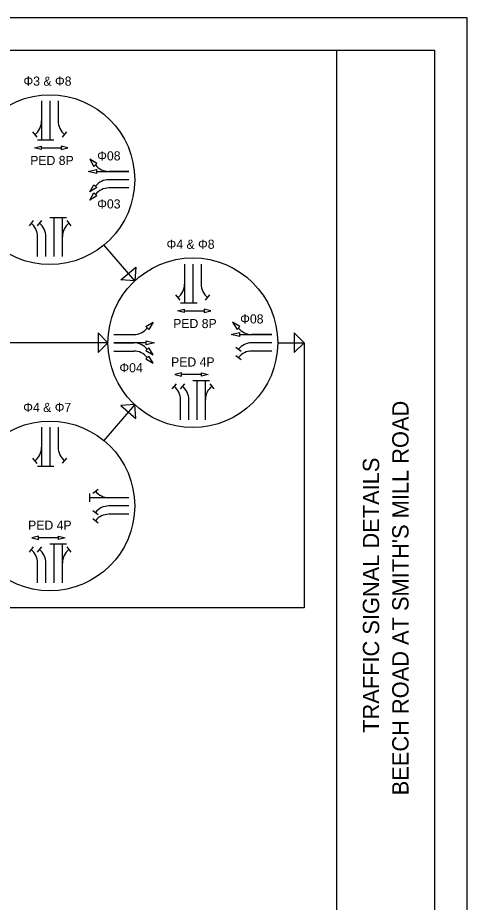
# Model space of a CAD drawing. Extents: x 0 to 34, y 0 to 22.
# Drawn here: x 27.11 to 34, y 8.45 to 22 of the extents above; entities that cross this region are included whole.
import ezdxf

# ---------------------------------------------------------------- set-up
doc = ezdxf.new("R2010")
doc.units = 0
for name, color, linetype in [('SG_P_Text', 7, 'Continuous'), ('SH_Border', 7, 'Continuous'), ('SH_Cut_Line', 7, 'Continuous'), ('SH_Data', 7, 'Continuous')]:
    doc.layers.add(name, color=color, linetype=linetype)

msp = doc.modelspace()

# ---------------------------------------------------------------- linework, layer by layer
at = {"layer": 'SG_P_Text'}
for p, q in [((27.479, 20.724), (27.479, 20.123)), ((27.479, 20.724), (27.479, 20.418)), ((27.606, 20.724), (27.606, 20.123)), ((27.733, 20.724), (27.733, 20.418)), ((27.412, 20.172), (27.348, 20.251)), ((27.8, 20.172), (27.864, 20.252)), ((27.543, 20.123), (27.416, 20.123)), ((27.669, 20.123), (27.543, 20.123)), ((27.474, 20.006), (27.779, 20.006)), ((28.319, 19.645), (28.817, 19.645)), ((28.817, 19.645), (28.511, 19.645)), ((28.817, 19.518), (28.511, 19.518)), ((28.817, 19.392), (28.511, 19.392)), ((27.351, 18.891), (27.287, 18.811)), ((27.477, 18.891), (27.413, 18.811)), ((27.608, 18.94), (27.735, 18.94)), ((27.671, 18.339), (27.671, 18.94)), ((27.735, 18.94), (27.861, 18.94)), ((27.798, 18.339), (27.798, 18.94)), ((27.865, 18.891), (27.929, 18.811)), ((27.418, 18.339), (27.418, 18.645)), ((27.544, 18.339), (27.544, 18.645)), ((27.798, 18.339), (27.798, 18.645)), ((28.906, 17.966), (28.435, 18.518)), ((29.669, 18.225), (29.669, 17.624)), ((29.669, 18.225), (29.669, 17.919)), ((29.796, 18.225), (29.796, 17.624)), ((29.923, 18.225), (29.923, 17.92)), ((29.602, 17.673), (29.538, 17.753)), ((29.733, 17.624), (29.606, 17.624)), ((29.86, 17.624), (29.733, 17.624)), ((29.99, 17.673), (30.054, 17.753)), ((29.665, 17.507), (29.97, 17.507)), ((28.586, 17.146), (28.891, 17.146)), ((30.509, 17.146), (31.007, 17.146)), ((31.007, 17.146), (30.701, 17.146)), ((28.496, 17.02), (26.716, 17.02)), ((29.083, 17.02), (28.585, 17.02)), ((28.586, 17.02), (28.891, 17.02)), ((30.455, 16.953), (30.535, 16.889)), ((31.007, 17.02), (30.701, 17.02)), ((28.585, 16.893), (28.891, 16.893)), ((30.455, 16.826), (30.535, 16.762)), ((31.007, 16.893), (30.701, 16.893)), ((29.928, 16.532), (29.623, 16.532)), ((29.798, 16.441), (29.925, 16.441)), ((29.861, 15.84), (29.861, 16.441)), ((29.925, 16.441), (30.052, 16.441)), ((29.988, 15.84), (29.988, 16.441)), ((29.541, 16.392), (29.477, 16.312)), ((29.668, 16.392), (29.604, 16.312)), ((30.055, 16.392), (30.119, 16.312)), ((29.608, 15.84), (29.608, 16.146)), ((29.735, 15.84), (29.735, 16.146)), ((29.988, 15.84), (29.988, 16.146)), ((28.906, 16.073), (28.435, 15.52)), ((27.479, 15.724), (27.479, 15.124)), ((27.479, 15.724), (27.479, 15.419)), ((27.606, 15.724), (27.606, 15.124)), ((27.733, 15.725), (27.733, 15.419)), ((27.412, 15.172), (27.348, 15.252)), ((27.8, 15.173), (27.864, 15.253)), ((27.543, 15.124), (27.416, 15.124)), ((27.669, 15.124), (27.543, 15.124)), ((28.265, 14.713), (28.344, 14.777)), ((28.216, 14.583), (28.216, 14.709)), ((28.817, 14.646), (28.216, 14.646)), ((28.817, 14.646), (28.511, 14.646)), ((28.817, 14.519), (28.511, 14.519)), ((28.265, 14.452), (28.344, 14.388)), ((28.817, 14.392), (28.511, 14.392)), ((28.265, 14.325), (28.344, 14.261)), ((27.738, 14.032), (27.433, 14.032)), ((27.351, 13.892), (27.287, 13.812)), ((27.477, 13.892), (27.413, 13.812)), ((27.608, 13.94), (27.735, 13.94)), ((27.671, 13.34), (27.671, 13.94)), ((27.735, 13.94), (27.861, 13.94)), ((27.798, 13.34), (27.798, 13.94)), ((27.865, 13.892), (27.929, 13.812)), ((27.418, 13.34), (27.418, 13.645)), ((27.544, 13.34), (27.544, 13.645)), ((27.798, 13.34), (27.798, 13.645))]:
    msp.add_line(p, q, dxfattribs=at)
for points in [[(27.474, 19.98), (27.37, 20.006), (27.474, 20.032)], [(27.779, 19.98), (27.884, 20.006), (27.779, 20.032)], [(28.327, 19.766), (28.216, 19.832), (28.282, 19.722)], [(28.319, 19.614), (28.194, 19.645), (28.319, 19.676)], [(28.327, 19.397), (28.216, 19.331), (28.282, 19.441)], [(28.327, 19.27), (28.216, 19.204), (28.282, 19.315)], [(28.906, 17.966), (28.692, 17.983), (28.923, 18.18)], [(29.665, 17.481), (29.56, 17.507), (29.665, 17.533)], [(29.97, 17.481), (30.074, 17.507), (29.97, 17.533)], [(29.076, 17.267), (29.186, 17.333), (29.12, 17.223)], [(30.517, 17.267), (30.406, 17.333), (30.473, 17.223)], [(28.496, 17.02), (28.345, 17.171), (28.345, 16.868)], [(30.509, 17.115), (30.384, 17.146), (30.509, 17.178)], [(31.502, 17.02), (31.35, 17.171), (31.35, 16.868)], [(29.076, 16.899), (29.186, 16.832), (29.12, 16.943)], [(29.083, 17.051), (29.208, 17.02), (29.083, 16.988)], [(29.075, 16.772), (29.186, 16.706), (29.12, 16.816)], [(29.623, 16.558), (29.519, 16.532), (29.623, 16.506)], [(29.928, 16.558), (30.032, 16.532), (29.928, 16.506)], [(28.906, 16.073), (28.692, 16.056), (28.923, 15.859)], [(27.433, 14.058), (27.328, 14.032), (27.433, 14.006)], [(27.738, 14.058), (27.842, 14.032), (27.738, 14.006)]]:
    msp.add_lwpolyline(points, close=True, dxfattribs=at)
msp.add_lwpolyline([(31.096, 17.02), (31.502, 17.02), (31.502, 12.958), (15.336, 12.958), (14.93, 12.958), (14.93, 17.02), (15.336, 17.02)], dxfattribs=at)
for centre in [(27.606, 19.518), (29.796, 17.02), (27.606, 14.519)]:
    msp.add_circle(centre, 1.3, dxfattribs=at)
for centre, start, end in [((27.214, 20.418), 308.7993, 0), ((27.998, 20.418), 180, 231.2007), ((28.511, 19.91), 218.8122, 270.0129), ((28.511, 19.253), 90, 141.2007), ((28.511, 19.126), 90, 141.2007), ((27.153, 18.645), 360, 51.2007), ((27.279, 18.645), 360, 51.2007), ((28.063, 18.645), 128.7993, 180), ((29.404, 17.919), 308.7993, 0), ((30.188, 17.92), 180, 231.2007), ((28.891, 17.411), 269.9871, 321.1878), ((30.701, 17.411), 218.8122, 270.0129), ((28.891, 16.755), 38.8122, 90.0129), ((30.701, 16.755), 90, 141.2007), ((28.891, 16.628), 38.8122, 90.0129), ((30.701, 16.628), 90, 141.2007), ((29.343, 16.146), 360, 51.2007), ((29.47, 16.146), 360, 51.2007), ((30.253, 16.146), 128.7993, 180), ((27.214, 15.419), 308.7993, 0), ((27.998, 15.419), 180, 231.2007), ((28.511, 14.911), 218.7993, 270), ((28.511, 14.254), 90, 141.2007), ((28.511, 14.127), 90, 141.2007), ((27.153, 13.645), 360, 51.2007), ((27.279, 13.645), 360, 51.2007), ((28.063, 13.645), 128.7993, 180)]:
    msp.add_arc(centre, 0.265, start, end, dxfattribs=at)
at = {"layer": 'SH_Border'}
msp.add_line((32, 0.5), (32, 21.5), dxfattribs=at)
msp.add_lwpolyline([(1.5, 21.5), (33.5, 21.5), (33.5, 0.5), (1.5, 0.5)], close=True, dxfattribs=at)
at = {"layer": 'SH_Cut_Line'}
msp.add_lwpolyline([(0, 0), (34, 0), (34, 22), (0, 22)], close=True, dxfattribs=at)

# ---------------------------------------------------------------- texts
at = {"layer": 'SG_P_Text'}
for s, p in [('Φ3 & Φ8', (27.202, 20.958)), ('Φ08', (28.331, 19.813)), ('Φ03', (28.331, 19.077)), ('Φ4 & Φ8', (29.393, 18.459)), ('Φ08', (30.521, 17.315)), ('Φ04', (28.671, 16.567)), ('Φ4 & Φ7', (27.198, 15.959))]:
    msp.add_text(s, height=0.14, dxfattribs=at).set_placement(p)
for s, p in [('PED 8P', (27.305, 19.743)), ('PED 8P', (29.495, 17.244)), ('PED 4P', (29.463, 16.655)), ('PED 4P', (27.273, 14.154))]:
    msp.add_text(s, height=0.14, rotation=360, dxfattribs=at).set_placement(p)
at = {"layer": 'SH_Data'}
for s, p in [("BEECH ROAD AT SMITH'S MILL ROAD", (33.1, 10.086)), ('TRAFFIC SIGNAL DETAILS', (32.65, 11.043))]:
    msp.add_text(s, height=0.25, rotation=90, dxfattribs=at).set_placement(p)

doc.saveas('drawing.dxf')
